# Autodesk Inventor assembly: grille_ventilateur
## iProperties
Created: 2011-01
Part Number: grille_ventilateur
Document SubType Name: Assembly
Designer: eric
Mass: 2.44231 g
Surface Area: 54.3754 cm^2
Volume: 2.44231 cm^3
Density: 1 g/cm^3
Norme de conversion: IGES 5.3
Nom du fichier: No Iges File Name specified
Préprocesseur: Autodesk Inventor 2011
Postprocesseur: Build: 342, Release: 2008 SP3 - Date: Tue 05/27/2008
Unités envoyées: MM
Incertitude: 0.01
Author: eric
